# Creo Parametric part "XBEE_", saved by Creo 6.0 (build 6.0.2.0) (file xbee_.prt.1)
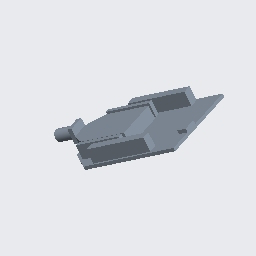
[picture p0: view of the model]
Units: Inch lbm Second (Pro/E Default); INCH, POUND, SECS

Created from: INLBS_PART_SOLID.PRT

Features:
  1. datum plane "RIGHT"
  2. datum plane "TOP"
  3. datum plane "FRONT"
  4. coordinate system
  5. sketch "Sketch 1"
  6. extrusion "Extrude 1"
  7. sketch "Sketch 2"
  8. extrusion "Extrude 2"
  9. sketch "Sketch 3"
  10. extrusion "Extrude 3"
  11. sketch "Sketch 4"
  12. extrusion "Extrude 4"
  13. sketch "Sketch 5"
  14. extrusion "Extrude 5"
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
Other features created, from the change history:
  sketch "Sketch 6"
  extrusion "Extrude 6"
  sketch "Sketch 7"
  extrusion "Extrude 7"

Surfaces: 44 plane, 1 cylinder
